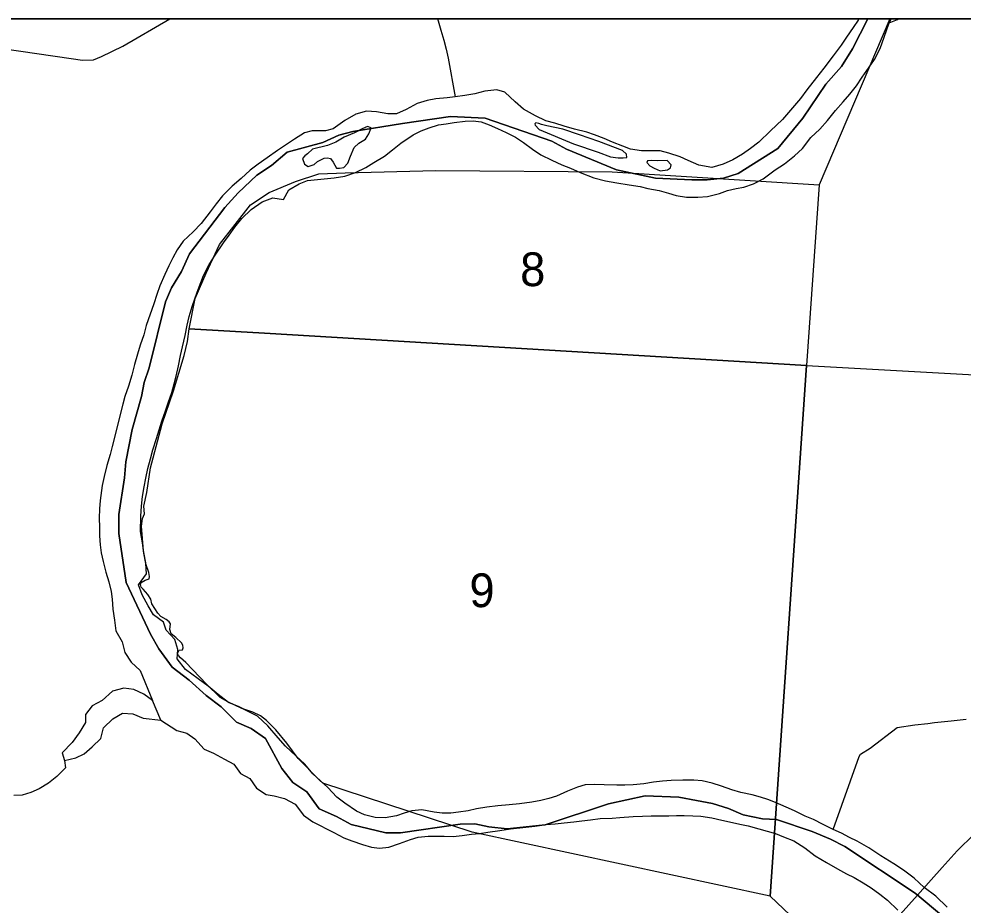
# Model space of a CAD drawing. Extents: x 0 to 34, y 0 to 22.
# Drawn here: x 3.839 to 5.01, y 19.8 to 20.9 of the extents above; entities that cross this region are included whole.
import ezdxf

# ---------------------------------------------------------------- set-up
doc = ezdxf.new("R2010")
doc.units = 0
for name, color, linetype in [('GM_X_Corporation', 7, 'Continuous'), ('GM_X_Major_River', 7, 'Continuous'), ('GM_X_Minor_River', 7, 'Continuous'), ('GM_X_Section_Text', 7, 'Continuous'), ('GM_X_State_Route', 7, 'Continuous'), ('GM_X_Township_Road', 7, 'Continuous'), ('SH_Data', 7, 'Continuous')]:
    doc.layers.add(name, color=color, linetype=linetype)

msp = doc.modelspace()

# ---------------------------------------------------------------- linework, layer by layer
at = {"layer": 'GM_X_Corporation'}
for points in [[(4.9836, 19.7878), (4.9535, 19.8132), (4.9509, 19.8154), (4.8636, 19.873), (4.8459, 19.8824), (4.823, 19.8919), (4.7787, 19.9066), (4.7616, 19.9076), (4.7373, 19.9124), (4.7192, 19.9201), (4.6995, 19.9264), (4.6798, 19.9303), (4.6578, 19.9343), (4.616, 19.9362), (4.5704, 19.9259), (4.4919, 19.8999), (4.4448, 19.895), (4.422, 19.8975), (4.4046, 19.9014), (4.3864, 19.9008), (4.3126, 19.89), (4.2944, 19.8901), (4.2512, 19.9004), (4.2331, 19.9104), (4.2117, 19.9197), (4.1962, 19.9409), (4.1789, 19.9524), (4.1653, 19.97), (4.1452, 20.0073), (4.1271, 20.0196), (4.109, 20.0274), (4.0902, 20.0465), (4.0713, 20.0603), (4.0503, 20.0794), (4.0292, 20.0955), (4.0127, 20.1184), (4.0022, 20.1367), (3.9723, 20.2007), (3.9629, 20.2616), (3.9631, 20.2851), (3.9702, 20.3306), (3.9719, 20.3503), (3.9797, 20.3905), (3.9913, 20.4314), (3.9945, 20.4489), (4.0007, 20.467), (4.0209, 20.5489), (4.0286, 20.5663), (4.0409, 20.5867), (4.0509, 20.6086), (4.0944, 20.666), (4.1112, 20.6841), (4.1341, 20.706), (4.1523, 20.718), (4.1721, 20.7345), (4.2163, 20.7467), (4.2359, 20.7557), (4.2534, 20.7601), (4.315, 20.7703), (4.3743, 20.7789), (4.4176, 20.777), (4.5001, 20.7482), (4.5183, 20.7382), (4.5804, 20.7126), (4.6289, 20.7023), (4.6737, 20.7005), (4.6927, 20.7003), (4.7132, 20.7024), (4.7315, 20.7083), (4.7803, 20.7391), (4.8117, 20.7769), (4.8402, 20.8192), (4.8593, 20.8411), (4.8732, 20.863), (4.892, 20.9), (2.1, 20.9)], [(8.9, 20.9), (4.892, 20.9), (4.8732, 20.863), (4.8593, 20.8411), (4.8402, 20.8192), (4.8117, 20.7769), (4.7803, 20.7391), (4.7315, 20.7083), (4.7132, 20.7024), (4.6927, 20.7003), (4.6737, 20.7005), (4.6289, 20.7023), (4.5804, 20.7126), (4.5183, 20.7382), (4.5001, 20.7482), (4.4176, 20.777), (4.3743, 20.7789), (4.315, 20.7703), (4.2534, 20.7601), (4.2359, 20.7557), (4.2163, 20.7467), (4.1721, 20.7345), (4.1523, 20.718), (4.1341, 20.706), (4.1112, 20.6841), (4.0944, 20.666), (4.0509, 20.6086), (4.0409, 20.5867), (4.0286, 20.5663), (4.0209, 20.5489), (4.0007, 20.467), (3.9945, 20.4489), (3.9913, 20.4314), (3.9797, 20.3905), (3.9719, 20.3503), (3.9702, 20.3306), (3.9631, 20.2851), (3.9629, 20.2616), (3.9723, 20.2007), (4.0022, 20.1367), (4.0127, 20.1184), (4.0292, 20.0955), (4.0503, 20.0794), (4.0713, 20.0603), (4.0902, 20.0465), (4.109, 20.0274), (4.1271, 20.0196), (4.1452, 20.0073), (4.1653, 19.97), (4.1789, 19.9524), (4.1962, 19.9409), (4.2117, 19.9197), (4.2331, 19.9104), (4.2512, 19.9004), (4.2944, 19.8901), (4.3126, 19.89), (4.3864, 19.9008), (4.4046, 19.9014), (4.422, 19.8975), (4.4448, 19.895), (4.4919, 19.8999), (4.5704, 19.9259), (4.616, 19.9362), (4.6578, 19.9343), (4.6798, 19.9303), (4.6995, 19.9264), (4.7192, 19.9201), (4.7373, 19.9124), (4.7616, 19.9076), (4.7787, 19.9066), (4.823, 19.8919), (4.8459, 19.8824), (4.8636, 19.873), (4.9509, 19.8154), (4.9535, 19.8132), (4.9836, 19.7878)]]:
    msp.add_lwpolyline(points, dxfattribs=at)
for points in [[(5.849, 20.9), (4.9193, 20.9), (4.8316, 20.6941), (4.8161, 20.4698), (5.8125, 20.4147), (5.8133, 20.4283)], [(4.0502, 20.5156), (4.0579, 20.553), (4.0716, 20.5845), (4.088, 20.6201), (4.1072, 20.6447), (4.1263, 20.6693), (4.1496, 20.6844), (4.1824, 20.6981), (4.2112, 20.7076), (4.244, 20.709), (4.3562, 20.7118), (4.5751, 20.7104), (4.8316, 20.6941), (4.8161, 20.4698), (4.1437, 20.5101)], [(4.0502, 20.5156), (4.1437, 20.5101), (4.8161, 20.4698), (4.7709, 19.8114), (4.4012, 19.8908), (4.2162, 19.9519), (4.2119, 19.9555), (4.1855, 19.9822), (4.1716, 20.0012), (4.1577, 20.018), (4.1464, 20.0294), (4.1389, 20.0352), (4.1294, 20.0398), (4.1158, 20.0444), (4.0981, 20.0528), (4.0887, 20.0582), (4.0717, 20.0746), (4.0461, 20.1013), (4.0397, 20.1074), (4.0371, 20.11), (4.036, 20.1127), (4.038, 20.1166), (4.0421, 20.1172), (4.0428, 20.1198), (4.0425, 20.1229), (4.041, 20.1259), (4.0338, 20.1324), (4.0282, 20.137), (4.0263, 20.1423), (4.0271, 20.1495), (4.0256, 20.1521), (4.0218, 20.1548), (4.0154, 20.1586), (4.0113, 20.1625), (4.0041, 20.1742), (4.0027, 20.1799), (3.9989, 20.186), (3.9933, 20.1925), (3.991, 20.1948), (3.9899, 20.1982), (3.9907, 20.2008), (3.9956, 20.2035), (4.0006, 20.2053), (4.0013, 20.208), (4.0002, 20.2129), (3.9972, 20.2228), (3.9936, 20.2402), (3.9925, 20.2554), (3.9911, 20.2705), (3.9923, 20.28), (3.995, 20.286), (3.9943, 20.2955), (3.9978, 20.3125), (4.0025, 20.3428), (4.0111, 20.3757), (4.0169, 20.3977), (4.0308, 20.4385), (4.0443, 20.4823), (4.0482, 20.4997)], [(4.8161, 20.4698), (5.8125, 20.4147), (5.7537, 19.4608), (5.102, 19.4969), (4.7709, 19.8114)]]:
    msp.add_lwpolyline(points, close=True, dxfattribs=at)
at = {"layer": 'GM_X_Major_River'}
for p, q in [((4.9211, 20.9), (4.9187, 20.8951)), ((4.015, 20.0299), (4.005, 20.0543))]:
    msp.add_line(p, q, dxfattribs=at)
for points in [[(4.2177, 20.7014), (4.2302, 20.7029), (4.2435, 20.7048), (4.2568, 20.7093), (4.2694, 20.7158), (4.2796, 20.7218), (4.2926, 20.7298), (4.3024, 20.7374), (4.3127, 20.7457), (4.3283, 20.7563), (4.3382, 20.7609), (4.3481, 20.765), (4.3598, 20.7684), (4.3693, 20.7699), (4.3792, 20.7714), (4.3925, 20.7729), (4.4028, 20.7737), (4.4126, 20.7721), (4.4225, 20.7687), (4.4328, 20.7641), (4.4434, 20.7592), (4.4552, 20.7531), (4.465, 20.7466), (4.476, 20.7382), (4.4866, 20.7314), (4.5003, 20.7249), (4.5124, 20.7191), (4.5234, 20.7149), (4.5352, 20.7096), (4.5523, 20.7027), (4.5667, 20.6989), (4.5808, 20.6966), (4.596, 20.6943), (4.6096, 20.692), (4.6191, 20.6897), (4.6335, 20.687), (4.6449, 20.6836), (4.6544, 20.6809), (4.6673, 20.6786), (4.6814, 20.6786), (4.6932, 20.6797), (4.708, 20.6835), (4.7182, 20.6872), (4.7289, 20.6895), (4.7384, 20.6914), (4.7505, 20.6955), (4.7623, 20.7016), (4.7771, 20.7126), (4.7886, 20.7202), (4.8011, 20.73), (4.811, 20.7391), (4.8213, 20.7528), (4.8327, 20.763), (4.8422, 20.774), (4.8521, 20.7862), (4.8616, 20.7972), (4.87, 20.8067), (4.878, 20.8169), (4.8852, 20.8275), (4.8936, 20.8401), (4.9004, 20.8496), (4.9073, 20.8632), (4.9122, 20.8773), (4.9187, 20.8951)], [(4.8807, 20.9), (4.88, 20.8986), (4.8739, 20.8891), (4.8655, 20.8774), (4.8591, 20.8675), (4.8492, 20.8542), (4.8377, 20.839), (4.8286, 20.8273), (4.8164, 20.8121), (4.8088, 20.8011), (4.7985, 20.7897), (4.7864, 20.7753), (4.7712, 20.7613), (4.7571, 20.7472), (4.7468, 20.7393), (4.7365, 20.7321), (4.7248, 20.7252), (4.7126, 20.7199), (4.6985, 20.7158), (4.6826, 20.7185), (4.6693, 20.7242), (4.6594, 20.7288), (4.6454, 20.7334), (4.6344, 20.7364), (4.6215, 20.7364), (4.6112, 20.7361), (4.5979, 20.7384), (4.5884, 20.7422), (4.5755, 20.7472), (4.5649, 20.7517), (4.5531, 20.7563), (4.5437, 20.7594), (4.5285, 20.7632), (4.5156, 20.767), (4.5038, 20.7705), (4.4928, 20.7735), (4.4799, 20.7796), (4.4651, 20.788), (4.4548, 20.7971), (4.4419, 20.809), (4.4321, 20.812), (4.4169, 20.8105), (4.4047, 20.8071), (4.3922, 20.8049), (4.3804, 20.8034), (4.3702, 20.8022), (4.3561, 20.8007), (4.3455, 20.7989), (4.3333, 20.7951), (4.3196, 20.7875), (4.3075, 20.7822), (4.2968, 20.7822), (4.2828, 20.7845), (4.2702, 20.7853), (4.2569, 20.7819), (4.2436, 20.774), (4.2288, 20.7637), (4.2193, 20.7611)], [(4.9187, 20.8951), (4.929, 20.8993), (4.9303, 20.9)], [(4.2177, 20.7273), (4.2219, 20.7276), (4.2257, 20.7269), (4.2291, 20.7223), (4.2329, 20.7147), (4.2367, 20.7147), (4.242, 20.7158), (4.247, 20.7208), (4.2504, 20.7295), (4.255, 20.7405), (4.2607, 20.7458), (4.269, 20.7507), (4.2732, 20.7572), (4.2759, 20.7648), (4.2714, 20.7663), (4.2649, 20.7637), (4.2554, 20.7587), (4.2425, 20.7531), (4.2322, 20.747), (4.2219, 20.7428)], [(4.484, 20.7701), (4.4805, 20.7709), (4.4793, 20.7697), (4.4797, 20.7681), (4.4844, 20.7629)], [(4.4844, 20.7629), (4.5269, 20.745), (4.5577, 20.7346), (4.5728, 20.7289), (4.5823, 20.7278), (4.5888, 20.7278), (4.593, 20.7281), (4.5926, 20.7323), (4.5877, 20.7365), (4.5584, 20.7479), (4.5345, 20.756), (4.5137, 20.7632), (4.4939, 20.7674), (4.4875, 20.769), (4.484, 20.7701)], [(4.2193, 20.7611), (4.2031, 20.7611), (4.1933, 20.7588), (4.1811, 20.7506), (4.1697, 20.7435), (4.1601, 20.7367), (4.1472, 20.7274), (4.1361, 20.7199), (4.1262, 20.7124), (4.1147, 20.7019), (4.1037, 20.6925), (4.0918, 20.6805), (4.0838, 20.6707), (4.0765, 20.6605), (4.0654, 20.6462), (4.0554, 20.6357), (4.0428, 20.624), (4.0355, 20.6135), (4.0302, 20.6037), (4.0251, 20.5935), (4.0201, 20.5829), (4.0139, 20.5689), (4.0101, 20.5579), (4.0065, 20.5466), (3.9972, 20.5194), (3.9941, 20.508), (3.9894, 20.4952), (3.9863, 20.4838), (3.9824, 20.4713), (3.9793, 20.4581), (3.975, 20.4445), (3.9707, 20.4316), (3.968, 20.4218), (3.9617, 20.3976), (3.9585, 20.3839), (3.955, 20.3696), (3.9523, 20.3597), (3.9484, 20.3457), (3.9448, 20.3321), (3.9425, 20.3211), (3.94, 20.3026), (3.9392, 20.2919), (3.9387, 20.2806), (3.939, 20.2692), (3.9393, 20.2586), (3.94, 20.2476), (3.941, 20.2377), (3.9436, 20.2267), (3.9469, 20.2134), (3.9506, 20.2016), (3.9535, 20.1894), (3.9549, 20.1799), (3.9556, 20.1678), (3.9577, 20.1541), (3.9595, 20.1408), (3.9673, 20.1271), (3.9706, 20.1138), (3.9785, 20.1019), (3.9894, 20.0916), (4.005, 20.0543)], [(4.2219, 20.7428), (4.2034, 20.7382), (4.1973, 20.7326), (4.1938, 20.73), (4.1908, 20.7266), (4.1934, 20.7197), (4.1979, 20.7167), (4.2055, 20.7192), (4.2097, 20.723), (4.2177, 20.7273)], [(4.6237, 20.7243), (4.619, 20.7238), (4.618, 20.7217), (4.6218, 20.7178)], [(4.6218, 20.7178), (4.6271, 20.7148), (4.6347, 20.7113), (4.6438, 20.7125), (4.6473, 20.7151), (4.6484, 20.7189), (4.6431, 20.7242), (4.6317, 20.7239), (4.6237, 20.7243)], [(4.2225, 19.9463), (4.2036, 19.9633), (4.1938, 19.9752), (4.1826, 19.9855), (4.1698, 19.9978), (4.1608, 20.0081), (4.148, 20.023), (4.1352, 20.0349), (4.1228, 20.0411), (4.1122, 20.0465), (4.099, 20.0519), (4.0862, 20.0619), (4.0741, 20.0722), (4.0613, 20.0811), (4.0459, 20.0926), (4.0354, 20.106), (4.0363, 20.1177), (4.0326, 20.1299), (4.022, 20.1414), (4.0187, 20.1513), (4.0063, 20.1605), (3.9996, 20.1719), (3.9921, 20.1853), (3.9877, 20.1978), (3.9976, 20.2114), (3.9966, 20.2243), (3.9941, 20.2372), (3.9923, 20.2501), (3.9901, 20.2638), (3.9903, 20.2831), (3.9911, 20.2953), (3.9924, 20.3074), (3.9944, 20.3195), (3.9964, 20.3301), (3.9991, 20.3422), (4.0023, 20.3543), (4.0054, 20.3653), (4.0097, 20.3793), (4.0132, 20.3903), (4.0163, 20.4009), (4.021, 20.4137), (4.0248, 20.4247), (4.0287, 20.4364), (4.0319, 20.447), (4.0342, 20.4568), (4.037, 20.4697), (4.0397, 20.4822), (4.0421, 20.4932), (4.0452, 20.5072), (4.048, 20.52), (4.0504, 20.5306), (4.0539, 20.5431), (4.0578, 20.5541), (4.0617, 20.5643), (4.0682, 20.5817), (4.0752, 20.5953), (4.0825, 20.607), (4.0928, 20.622), (4.1001, 20.6318), (4.107, 20.6416), (4.1158, 20.6522), (4.1273, 20.6634), (4.1407, 20.6732), (4.1543, 20.678), (4.1672, 20.676), (4.1741, 20.6877), (4.1867, 20.6955), (4.1973, 20.6996), (4.2177, 20.7014)], [(4.005, 20.0543), (3.9941, 20.062), (3.9816, 20.0681), (3.9691, 20.0698), (3.9551, 20.0657), (3.9425, 20.0541), (3.9299, 20.0478), (3.9219, 20.0368), (3.9218, 20.027), (3.9137, 20.0142), (3.9053, 20.0021), (3.8927, 19.9893), (3.8956, 19.9798), (3.9097, 19.9831), (3.9199, 19.9883), (3.9299, 19.9966), (3.9409, 20.0071), (3.9441, 20.0203), (3.9555, 20.0316), (3.9677, 20.0387), (3.9806, 20.0378), (3.9931, 20.0324), (4.015, 20.0299)], [(4.015, 20.0299), (4.035, 20.0172), (4.0475, 20.0137), (4.0573, 20.0068), (4.0689, 19.9941), (4.0806, 19.9891), (4.0942, 19.9814), (4.1059, 19.9752), (4.1142, 19.9638), (4.1255, 19.9576), (4.1337, 19.9454), (4.1458, 19.9377), (4.1556, 19.9361), (4.1685, 19.9329), (4.1817, 19.9256), (4.1922, 19.9122), (4.2038, 19.9038)], [(4.9906, 19.7979), (4.9766, 19.8116), (4.9621, 19.8223), (4.9496, 19.8337), (4.9363, 19.8436), (4.9242, 19.8516), (4.9083, 19.8615), (4.8935, 19.8714), (4.8787, 19.8798), (4.8692, 19.8844), (4.8593, 19.8897), (4.8491, 19.8943), (4.8366, 19.9004), (4.8248, 19.9065), (4.8145, 19.9107), (4.8013, 19.9172), (4.791, 19.9218), (4.7777, 19.9279), (4.7682, 19.9313), (4.7588, 19.9344), (4.7485, 19.9371), (4.7348, 19.9401), (4.7235, 19.9436), (4.7105, 19.9478), (4.6992, 19.9516), (4.6866, 19.9546), (4.6764, 19.9554), (4.6627, 19.9554), (4.6483, 19.9551), (4.6373, 19.9544), (4.6262, 19.9529), (4.6141, 19.951), (4.6012, 19.9495), (4.5909, 19.9491), (4.581, 19.9491), (4.5651, 19.9495), (4.5529, 19.9499), (4.5415, 19.9496), (4.532, 19.9469), (4.5195, 19.9416), (4.5058, 19.9356), (4.4963, 19.9329), (4.4864, 19.9303), (4.4754, 19.928), (4.4602, 19.9262), (4.4473, 19.925), (4.4333, 19.9236), (4.4196, 19.9221), (4.4067, 19.9198), (4.3964, 19.9175), (4.3846, 19.9157), (4.3751, 19.9145), (4.3641, 19.9146), (4.3542, 19.9157), (4.3391, 19.9188), (4.3265, 19.9173), (4.317, 19.9146), (4.3075, 19.9112), (4.2935, 19.9086), (4.2809, 19.909), (4.268, 19.9124), (4.2578, 19.917), (4.2434, 19.9269), (4.2335, 19.9345), (4.2225, 19.9463)], [(4.2038, 19.9038), (4.2296, 19.8905), (4.2422, 19.884), (4.252, 19.8802), (4.2653, 19.8756), (4.2763, 19.8725), (4.2866, 19.871), (4.298, 19.8725), (4.3113, 19.877), (4.3249, 19.8819), (4.3344, 19.8846), (4.3466, 19.8861), (4.3667, 19.886), (4.3777, 19.8857), (4.3891, 19.8868), (4.4005, 19.8883), (4.4104, 19.8894), (4.4207, 19.8909), (4.4355, 19.8928), (4.4488, 19.895), (4.4644, 19.8969), (4.4792, 19.8984), (4.4932, 19.9003), (4.5042, 19.9014), (4.5156, 19.9025), (4.5274, 19.9036), (4.5373, 19.9051), (4.5483, 19.9062), (4.5601, 19.9077), (4.5749, 19.9085), (4.5844, 19.9092), (4.6011, 19.9103), (4.6125, 19.9107), (4.6235, 19.9111), (4.6349, 19.911), (4.6452, 19.9114), (4.655, 19.9118), (4.6645, 19.9117), (4.6752, 19.9113), (4.685, 19.9106), (4.6987, 19.9086), (4.7109, 19.906), (4.7207, 19.9037), (4.7333, 19.901), (4.7439, 19.8987), (4.7568, 19.8952), (4.7674, 19.8922), (4.7777, 19.8891), (4.7875, 19.8853), (4.8004, 19.88), (4.8141, 19.8716), (4.827, 19.8617), (4.841, 19.8533), (4.8547, 19.8453), (4.8657, 19.8392), (4.8752, 19.8346), (4.8862, 19.8281), (4.8961, 19.8217), (4.9071, 19.814), (4.9165, 19.8064), (4.9294, 19.7942)]]:
    msp.add_lwpolyline(points, dxfattribs=at)
at = {"layer": 'GM_X_Minor_River'}
for points in [[(4.3582, 20.9), (4.359, 20.8977), (4.3627, 20.886), (4.3664, 20.8734), (4.369, 20.8624), (4.3717, 20.8514), (4.3804, 20.8034)], [(4.8491, 19.8943), (4.8813, 19.9849), (4.8832, 19.9879), (4.895, 19.9951), (4.9286, 20.0207), (4.9503, 20.0239), (4.9666, 20.0257), (4.975, 20.0268), (4.9956, 20.0289), (5.0142, 20.0311)], [(3.8956, 19.9798), (3.897, 19.9707), (3.8863, 19.9602), (3.876, 19.9519), (3.8642, 19.9448), (3.8539, 19.94), (3.8433, 19.937), (3.8327, 19.9364)]]:
    msp.add_lwpolyline(points, dxfattribs=at)
at = {"layer": 'GM_X_State_Route'}
for points in [[(5.2154, 19.9723), (5.1248, 19.9467), (5.1015, 19.9387), (5.0782, 19.9281), (5.0571, 19.9155), (5.0387, 19.9018), (5.0239, 19.8886), (5.0029, 19.8676), (4.9843, 19.8469)], [(4.9843, 19.8469), (4.9537, 19.8127), (4.8244, 19.6683)]]:
    msp.add_lwpolyline(points, dxfattribs=at)
at = {"layer": 'GM_X_Township_Road'}
msp.add_lwpolyline([(3.7236, 20.8751), (3.8187, 20.8634), (3.9038, 20.851), (3.9179, 20.8487), (3.9315, 20.8493), (3.9417, 20.8533), (3.9679, 20.866), (4.0265, 20.9)], dxfattribs=at)
at = {"layer": 'SH_Data'}
msp.add_line((2.1, 20.9), (8.9, 20.9), dxfattribs=at)

# ---------------------------------------------------------------- texts
at = {"layer": 'GM_X_Section_Text'}
for s, p in [('8', (4.4609, 20.5684)), ('9', (4.398, 20.1701))]:
    msp.add_text(s, height=0.0419, rotation=0, dxfattribs=at).set_placement(p)

doc.saveas('drawing.dxf')
